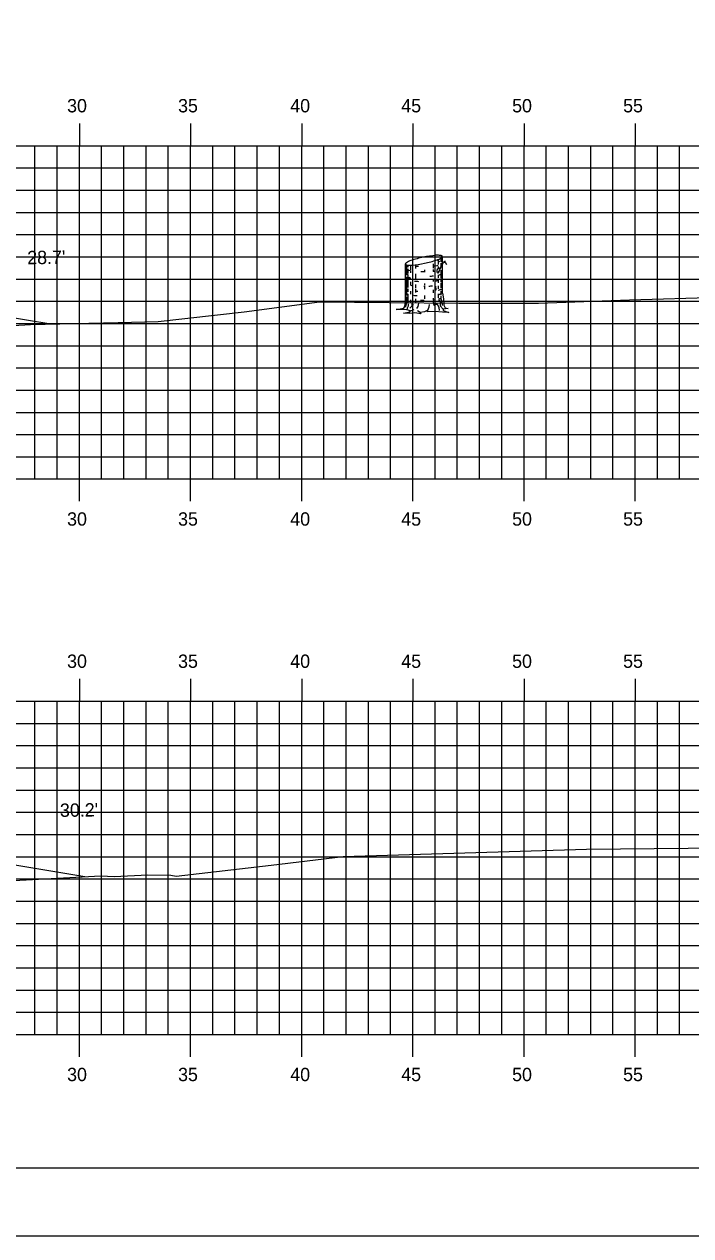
# Model space of a CAD drawing. Extents: x 1048565 to 1048735, y 781387 to 781497.
# Drawn here: x 1048675.4 to 1048705.4, y 781387.3 to 781441.8 of the extents above; entities that cross this region are included whole.
import ezdxf

# ---------------------------------------------------------------- set-up
doc = ezdxf.new("R2010")
doc.units = 0
for name, color, linetype in [('ANNOTATION', 7, 'Continuous'), ('BORDER', 7, 'Continuous'), ('D_Roadway_SlopeLines', 7, 'Continuous'), ('H_V ANNOTATION', 7, 'Continuous'), ('M_Trees_Conifer_Pay', 7, 'Continuous'), ('MAJOR', 7, 'Continuous'), ('MINOR', 7, 'Continuous'), ('PLOT BOUNDARY', 7, 'Continuous'), ('S_Roadway_Centerline', 7, 'Continuous')]:
    doc.layers.add(name, color=color, linetype=linetype)

msp = doc.modelspace()

# ---------------------------------------------------------------- linework, layer by layer
at = {"layer": 'BORDER'}
msp.add_lwpolyline([(1048572.876, 781390.375), (1048732.876, 781390.375), (1048732.876, 781495.375), (1048572.876, 781495.375)], close=True, dxfattribs=at)
at = {"layer": 'D_Roadway_SlopeLines'}
for points in [[(1048673.288, 781428.903), (1048676.593, 781428.352)], [(1048674.618, 781404.065), (1048678.119, 781403.481)]]:
    msp.add_lwpolyline(points, dxfattribs=at)
at = {"layer": 'M_Trees_Conifer_Pay'}
for p, q in [((1048692.54, 781429.33), (1048692.54, 781431.052)), ((1048692.587, 781431.015), (1048692.587, 781430.544)), ((1048692.645, 781431.004), (1048692.645, 781430.906)), ((1048692.771, 781430.996), (1048692.771, 781430.764)), ((1048692.991, 781431.016), (1048692.991, 781430.848)), ((1048693.787, 781431.058), (1048693.787, 781430.859)), ((1048694.015, 781431.254), (1048694.015, 781431.031)), ((1048694.015, 781430.943), (1048694.015, 781430.895)), ((1048694.132, 781431.315), (1048694.132, 781431.153)), ((1048694.132, 781431.085), (1048694.132, 781430.957)), ((1048694.204, 781429.741), (1048694.204, 781431.388)), ((1048692.587, 781430.479), (1048692.587, 781430.171)), ((1048692.645, 781430.832), (1048692.645, 781430.628)), ((1048692.645, 781430.57), (1048692.645, 781430.371)), ((1048692.771, 781430.723), (1048692.771, 781430.649)), ((1048692.991, 781430.611), (1048692.991, 781430.374)), ((1048693.396, 781430.785), (1048693.396, 781430.689)), ((1048693.787, 781430.801), (1048693.787, 781430.712)), ((1048693.787, 781430.365), (1048693.787, 781430.26)), ((1048694.015, 781430.56), (1048694.015, 781430.428)), ((1048694.072, 781430.76), (1048694.021, 781430.7)), ((1048694.132, 781430.77), (1048694.132, 781430.434)), ((1048694.132, 781430.397), (1048694.132, 781430.235)), ((1048692.587, 781430.124), (1048692.587, 781429.632)), ((1048692.645, 781430.323), (1048692.645, 781429.987)), ((1048692.645, 781429.934), (1048692.645, 781429.798)), ((1048692.771, 781430.245), (1048692.771, 781430.107)), ((1048692.771, 781429.835), (1048692.771, 781429.693)), ((1048692.991, 781430.13), (1048692.991, 781429.977)), ((1048692.991, 781429.934), (1048692.991, 781429.761)), ((1048693.396, 781430.171), (1048693.396, 781430.097)), ((1048693.396, 781430.072), (1048693.396, 781429.924)), ((1048693.787, 781429.893), (1048693.787, 781429.746)), ((1048694.015, 781430.317), (1048694.015, 781430.208)), ((1048694.015, 781430.072), (1048694.015, 781429.93)), ((1048694.132, 781430.187), (1048694.132, 781429.971)), ((1048694.132, 781429.94), (1048694.132, 781429.866)), ((1048694.132, 781429.825), (1048694.132, 781429.652)), ((1048692.587, 781429.578), (1048692.587, 781429.33)), ((1048692.645, 781429.699), (1048692.645, 781429.321)), ((1048692.771, 781429.432), (1048692.771, 781429.337)), ((1048692.991, 781429.483), (1048692.991, 781429.33)), ((1048693.396, 781429.632), (1048693.396, 781429.479)), ((1048693.787, 781429.514), (1048693.787, 781429.426)), ((1048694.015, 781429.703), (1048694.015, 781429.531)), ((1048692.771, 781428.937), (1048692.934, 781429.001)), ((1048693.208, 781428.873), (1048693.082, 781428.937))]:
    msp.add_line(p, q, dxfattribs=at)
for points in [[(1048694.021, 781430.886), (1048694.058, 781430.811), (1048694.105, 781430.869), (1048694.163, 781430.937), (1048694.255, 781431.13), (1048694.319, 781431.178), (1048694.35, 781431.184)], [(1048694.035, 781430.632), (1048694.072, 781430.76), (1048694.136, 781430.875), (1048694.166, 781430.943), (1048694.235, 781431.089)], [(1048694.25, 781431.119), (1048694.325, 781431.126), (1048694.397, 781431.027)], [(1048692.719, 781430.358), (1048692.713, 781430.453), (1048692.756, 781430.43), (1048692.756, 781430.336)], [(1048693.987, 781430.848), (1048693.957, 781430.764), (1048693.953, 781430.696), (1048693.983, 781430.632)], [(1048693.858, 781429.959), (1048693.871, 781429.882), (1048693.918, 781429.893), (1048693.905, 781430.059)], [(1048694.204, 781429.741), (1048694.255, 781429.479), (1048694.271, 781429.205), (1048694.329, 781429.08), (1048694.465, 781429.049), (1048694.235, 781429.012), (1048694.235, 781429.012), (1048694.241, 781428.964), (1048694.488, 781428.87), (1048694.214, 781428.886), (1048693.858, 781428.907), (1048693.537, 781428.896), (1048693.543, 781428.979), (1048693.395, 781428.896), (1048693.208, 781428.873), (1048693.232, 781428.806), (1048692.964, 781428.849), (1048692.744, 781428.822), (1048692.451, 781428.839), (1048692.74, 781428.896), (1048692.771, 781428.937), (1048692.608, 781428.995), (1048692.371, 781429.006), (1048692.13, 781429.006), (1048692.472, 781429.063), (1048692.514, 781429.143), (1048692.54, 781429.33)], [(1048692.588, 781429.283), (1048692.567, 781429.205), (1048692.546, 781429.111)], [(1048692.666, 781429.263), (1048692.672, 781429.147), (1048692.619, 781429.059), (1048692.608, 781428.995)], [(1048692.829, 781429.29), (1048692.829, 781429.158), (1048692.74, 781429.059)], [(1048693.055, 781429.049), (1048693.123, 781429.143), (1048693.149, 781429.283)], [(1048693.794, 781429.348), (1048693.804, 781429.222), (1048693.878, 781429.178)], [(1048694.031, 781429.453), (1048694.105, 781429.348), (1048694.109, 781429.174), (1048694.235, 781429.012)], [(1048694.13, 781429.598), (1048694.136, 781429.453), (1048694.183, 781429.384), (1048694.193, 781429.185)], [(1048693.543, 781428.979), (1048693.617, 781429.121), (1048693.627, 781429.222)], [(1048694.072, 781428.958), (1048694.058, 781429.096), (1048693.983, 781429.225)]]:
    msp.add_lwpolyline(points, dxfattribs=at)
for centre, radius, start, end in [((1048694.396, 781426.285), 5.179, 95.3794, 101.7194), ((1048693.985, 781430.643), 0.802, 79.2194, 95.3794), ((1048692.571, 781431.051), 0.0314, 156.5158, 169.2194), ((1048692.566, 781431.052), 0.0264, 169.2194, 180.0315), ((1048692.563, 781431.052), 0.0226, 180.0315, 191.7194), ((1048692.563, 781431.052), 0.0226, 191.7194, 203.4074), ((1048692.591, 781431.043), 0.0527, 146.7194, 156.5158), ((1048692.566, 781431.053), 0.0264, 203.4074, 214.2194), ((1048692.57, 781431.056), 0.0314, 214.2194, 226.923), ((1048692.615, 781431.027), 0.0817, 132.3887, 146.7194), ((1048692.585, 781431.072), 0.0527, 226.923, 236.7194), ((1048692.601, 781431.096), 0.0817, 236.7194, 251.0501), ((1048692.729, 781430.902), 0.251, 124.2194, 132.3887), ((1048692.656, 781431.256), 0.251, 251.0501, 259.2194), ((1048693.039, 781430.446), 0.802, 108.0594, 124.2194), ((1048692.759, 781431.797), 0.802, 259.2194, 275.3794), ((1048694.396, 781426.285), 5.179, 101.7194, 108.0594), ((1048692.348, 781436.155), 5.179, 275.3794, 281.7194), ((1048693.372, 781435.064), 4.124, 264.6955, 266.7331), ((1048692.348, 781436.155), 5.179, 281.7194, 288.0594), ((1048693.372, 781435.064), 4.124, 276.238, 278.1032), ((1048693.873, 781431.547), 0.571, 278.1032, 284.3667), ((1048693.705, 781431.993), 0.802, 288.0594, 304.2194), ((1048693.873, 781431.701), 0.571, 284.4317, 292.4132), ((1048693.873, 781431.547), 0.571, 297.0237, 300), ((1048694.088, 781431.184), 0.251, 71.0501, 79.2194), ((1048694.015, 781431.538), 0.251, 304.2194, 312.3887), ((1048694.072, 781431.356), 0.172, 300, 311.2506), ((1048694.072, 781431.202), 0.172, 300, 311.2506), ((1048694.143, 781431.344), 0.0817, 56.7194, 71.0501), ((1048694.129, 781431.413), 0.0817, 312.3887, 326.7194), ((1048694.145, 781431.273), 0.0624, 311.2506, 330), ((1048694.145, 781431.119), 0.0624, 311.2506, 330), ((1048694.159, 781431.368), 0.0527, 46.923, 56.7194), ((1048694.174, 781431.383), 0.0314, 34.2194, 46.923), ((1048694.153, 781431.397), 0.0527, 326.7194, 336.5158), ((1048694.16, 781431.264), 0.0441, 330, 343.9485), ((1048694.16, 781431.11), 0.0441, 330, 343.9485), ((1048694.178, 781431.386), 0.0264, 23.4074, 34.2194), ((1048694.173, 781431.389), 0.0314, 336.5158, 349.2194), ((1048694.181, 781431.388), 0.0226, 11.7194, 23.4074), ((1048694.181, 781431.388), 0.0226, 0.0315, 11.7194), ((1048694.178, 781431.388), 0.0264, 349.2194, 0.0315), ((1048694.171, 781431.261), 0.0334, 343.9485, 354.2151), ((1048694.171, 781431.107), 0.0334, 343.9485, 354.2151), ((1048692.572, 781430.874), 0.0334, 163.9485, 180), ((1048692.572, 781430.874), 0.0334, 180, 196.0515), ((1048692.572, 781430.427), 0.0334, 163.9485, 180), ((1048692.572, 781430.427), 0.0334, 180, 196.0515), ((1048692.582, 781430.877), 0.0441, 196.0515, 210), ((1048692.582, 781430.43), 0.0441, 196.0515, 210), ((1048692.598, 781430.886), 0.0624, 210, 228.7494), ((1048692.598, 781430.439), 0.0624, 210, 228.7494), ((1048692.671, 781430.969), 0.172, 228.7494, 240), ((1048692.671, 781430.522), 0.172, 228.7494, 240), ((1048692.87, 781431.314), 0.571, 240, 240.3367), ((1048692.87, 781430.867), 0.571, 240, 240.3367), ((1048692.871, 781431.103), 0.571, 240, 247.0587), ((1048692.87, 781431.314), 0.571, 246.8597, 257.9846), ((1048693.371, 781434.831), 4.124, 268.0751, 270), ((1048693.371, 781434.831), 4.124, 270, 270.3581), ((1048693.372, 781434.62), 4.124, 273.7052, 275.9504), ((1048693.371, 781434.831), 4.124, 275.7849, 277.0558), ((1048693.873, 781431.103), 0.571, 284.4493, 297.0429), ((1048693.871, 781430.867), 0.571, 297.1896, 300), ((1048694.071, 781430.522), 0.172, 300, 311.2506), ((1048694.143, 781430.439), 0.0624, 311.2506, 330), ((1048694.159, 781430.43), 0.0441, 330, 343.9485), ((1048694.169, 781430.427), 0.0334, 343.9485, 354.2151), ((1048694.171, 781430.663), 0.0334, 343.9485, 354.2151), ((1048692.572, 781430.217), 0.0334, 163.9485, 180), ((1048692.572, 781430.217), 0.0334, 180, 196.0515), ((1048692.572, 781429.98), 0.0334, 163.9485, 180), ((1048692.572, 781429.98), 0.0334, 180, 196.0515), ((1048692.582, 781430.22), 0.0441, 196.0515, 210), ((1048692.582, 781429.983), 0.0441, 196.0515, 210), ((1048692.598, 781430.229), 0.0624, 210, 228.7494), ((1048692.598, 781429.993), 0.0624, 210, 228.7494), ((1048692.671, 781430.312), 0.172, 228.7494, 240), ((1048692.671, 781430.075), 0.172, 228.7494, 240), ((1048692.87, 781430.657), 0.571, 240, 246.8597), ((1048692.87, 781430.42), 0.571, 240, 246.8597), ((1048692.87, 781430.657), 0.571, 259.2707, 261.8968), ((1048693.371, 781434.175), 4.124, 261.8968, 263.1474), ((1048693.371, 781434.385), 4.124, 264.081, 266.6676), ((1048693.371, 781433.938), 4.124, 264.716, 266.3193), ((1048693.371, 781434.175), 4.124, 270, 270.3581), ((1048693.371, 781434.175), 4.124, 273.1493, 275.4569), ((1048693.371, 781434.385), 4.124, 277.6125, 278.1032), ((1048693.871, 781430.867), 0.571, 278.1032, 286.9296), ((1048693.871, 781430.42), 0.571, 285.3983, 297.1896), ((1048693.871, 781430.657), 0.571, 297.1896, 300), ((1048694.071, 781430.312), 0.172, 300, 311.2506), ((1048694.143, 781430.229), 0.0624, 311.2506, 330), ((1048694.159, 781430.22), 0.0441, 330, 343.9485), ((1048694.169, 781430.217), 0.0334, 343.9485, 354.2151), ((1048692.572, 781429.783), 0.0334, 163.9485, 180), ((1048692.572, 781429.587), 0.0334, 163.9485, 180), ((1048692.572, 781429.587), 0.0334, 180, 196.0515), ((1048692.572, 781429.367), 0.0334, 163.9485, 180), ((1048692.572, 781429.367), 0.0334, 180, 196.0515), ((1048692.582, 781429.59), 0.0441, 196.0515, 210), ((1048692.582, 781429.37), 0.0441, 196.0515, 210), ((1048692.598, 781429.599), 0.0624, 210, 228.7494), ((1048692.598, 781429.379), 0.0624, 210, 228.7494), ((1048692.671, 781429.682), 0.172, 228.7494, 240), ((1048692.671, 781429.462), 0.172, 228.7494, 240), ((1048692.859, 781430.229), 0.571, 241.2369, 248.0268), ((1048692.87, 781430.027), 0.571, 240, 246.8597), ((1048692.87, 781429.807), 0.571, 240, 244.5314), ((1048693.371, 781433.74), 4.124, 263.4991, 265.8397), ((1048693.371, 781433.544), 4.124, 267.8117, 270), ((1048693.371, 781433.544), 4.124, 270, 270.1328), ((1048693.371, 781433.544), 4.124, 275.7849, 276.7896), ((1048693.871, 781430.027), 0.571, 288.5067, 297.2721), ((1048693.871, 781430.223), 0.571, 289.2907, 300), ((1048694.071, 781429.877), 0.172, 300, 311.2506), ((1048694.071, 781429.462), 0.172, 300, 311.2506), ((1048694.143, 781429.795), 0.0624, 311.2506, 330), ((1048694.143, 781429.379), 0.0624, 311.2506, 330), ((1048694.159, 781429.786), 0.0441, 330, 343.9485), ((1048694.159, 781429.37), 0.0441, 330, 343.9485), ((1048694.169, 781429.783), 0.0334, 343.9485, 354.2151), ((1048694.169, 781429.367), 0.0334, 343.9485, 354.2151), ((1048693.371, 781433.324), 4.124, 262.4438, 263.512), ((1048693.371, 781433.324), 4.124, 277.3684, 278.1032), ((1048693.871, 781429.807), 0.571, 278.1032, 281.637)]:
    msp.add_arc(centre, radius, start, end, dxfattribs=at)
at = {"layer": 'MAJOR'}
for p, q in [((1048677.876, 781437.377), (1048677.876, 781436.375)), ((1048682.876, 781437.377), (1048682.876, 781436.375)), ((1048687.876, 781437.377), (1048687.876, 781436.375)), ((1048692.876, 781437.377), (1048692.876, 781436.375)), ((1048697.876, 781437.377), (1048697.876, 781436.375)), ((1048702.876, 781437.377), (1048702.876, 781436.375)), ((1048577.876, 781436.375), (1048717.876, 781436.375)), ((1048577.876, 781436.375), (1048717.876, 781436.375)), ((1048677.876, 781421.375), (1048677.876, 781436.375)), ((1048682.876, 781421.375), (1048682.876, 781436.375)), ((1048687.876, 781421.375), (1048687.876, 781436.375)), ((1048692.876, 781421.375), (1048692.876, 781436.375)), ((1048697.876, 781421.375), (1048697.876, 781436.375)), ((1048702.876, 781421.375), (1048702.876, 781436.375)), ((1048577.876, 781431.375), (1048717.876, 781431.375)), ((1048577.876, 781426.375), (1048717.876, 781426.375)), ((1048577.876, 781421.375), (1048717.876, 781421.375)), ((1048577.876, 781421.375), (1048717.876, 781421.375)), ((1048677.876, 781420.373), (1048677.876, 781421.375)), ((1048682.876, 781420.373), (1048682.876, 781421.375)), ((1048687.876, 781420.373), (1048687.876, 781421.375)), ((1048692.876, 781420.373), (1048692.876, 781421.375)), ((1048697.876, 781420.373), (1048697.876, 781421.375)), ((1048702.876, 781420.373), (1048702.876, 781421.375)), ((1048677.876, 781412.377), (1048677.876, 781411.375)), ((1048682.876, 781412.377), (1048682.876, 781411.375)), ((1048687.876, 781412.377), (1048687.876, 781411.375)), ((1048692.876, 781412.377), (1048692.876, 781411.375)), ((1048697.876, 781412.377), (1048697.876, 781411.375)), ((1048702.876, 781412.377), (1048702.876, 781411.375)), ((1048577.876, 781411.375), (1048717.876, 781411.375)), ((1048577.876, 781411.375), (1048717.876, 781411.375)), ((1048677.876, 781396.375), (1048677.876, 781411.375)), ((1048682.876, 781396.375), (1048682.876, 781411.375)), ((1048687.876, 781396.375), (1048687.876, 781411.375)), ((1048692.876, 781396.375), (1048692.876, 781411.375)), ((1048697.876, 781396.375), (1048697.876, 781411.375)), ((1048702.876, 781396.375), (1048702.876, 781411.375)), ((1048577.876, 781406.375), (1048717.876, 781406.375)), ((1048577.876, 781401.375), (1048717.876, 781401.375)), ((1048577.876, 781396.375), (1048717.876, 781396.375)), ((1048577.876, 781396.375), (1048717.876, 781396.375)), ((1048677.876, 781395.373), (1048677.876, 781396.375)), ((1048682.876, 781395.373), (1048682.876, 781396.375)), ((1048687.876, 781395.373), (1048687.876, 781396.375)), ((1048692.876, 781395.373), (1048692.876, 781396.375)), ((1048697.876, 781395.373), (1048697.876, 781396.375)), ((1048702.876, 781395.373), (1048702.876, 781396.375))]:
    msp.add_line(p, q, dxfattribs=at)
at = {"layer": 'MINOR'}
for p, q in [((1048675.876, 781421.375), (1048675.876, 781436.375)), ((1048676.876, 781421.375), (1048676.876, 781436.375)), ((1048678.876, 781421.375), (1048678.876, 781436.375)), ((1048679.876, 781421.375), (1048679.876, 781436.375)), ((1048680.876, 781421.375), (1048680.876, 781436.375)), ((1048681.876, 781421.375), (1048681.876, 781436.375)), ((1048683.876, 781421.375), (1048683.876, 781436.375)), ((1048684.876, 781421.375), (1048684.876, 781436.375)), ((1048685.876, 781421.375), (1048685.876, 781436.375)), ((1048686.876, 781421.375), (1048686.876, 781436.375)), ((1048688.876, 781421.375), (1048688.876, 781436.375)), ((1048689.876, 781421.375), (1048689.876, 781436.375)), ((1048690.876, 781421.375), (1048690.876, 781436.375)), ((1048691.876, 781421.375), (1048691.876, 781436.375)), ((1048693.876, 781421.375), (1048693.876, 781436.375)), ((1048694.876, 781421.375), (1048694.876, 781436.375)), ((1048695.876, 781421.375), (1048695.876, 781436.375)), ((1048696.876, 781421.375), (1048696.876, 781436.375)), ((1048698.876, 781421.375), (1048698.876, 781436.375)), ((1048699.876, 781421.375), (1048699.876, 781436.375)), ((1048700.876, 781421.375), (1048700.876, 781436.375)), ((1048701.876, 781421.375), (1048701.876, 781436.375)), ((1048703.876, 781421.375), (1048703.876, 781436.375)), ((1048704.876, 781421.375), (1048704.876, 781436.375)), ((1048577.876, 781435.375), (1048717.876, 781435.375)), ((1048577.876, 781434.375), (1048717.876, 781434.375)), ((1048577.876, 781433.375), (1048717.876, 781433.375)), ((1048577.876, 781432.375), (1048717.876, 781432.375)), ((1048577.876, 781430.375), (1048717.876, 781430.375)), ((1048577.876, 781429.375), (1048717.876, 781429.375)), ((1048577.876, 781428.375), (1048717.876, 781428.375)), ((1048577.876, 781427.375), (1048717.876, 781427.375)), ((1048577.876, 781425.375), (1048717.876, 781425.375)), ((1048577.876, 781424.375), (1048717.876, 781424.375)), ((1048577.876, 781423.375), (1048717.876, 781423.375)), ((1048577.876, 781422.375), (1048717.876, 781422.375)), ((1048675.876, 781396.375), (1048675.876, 781411.375)), ((1048676.876, 781396.375), (1048676.876, 781411.375)), ((1048678.876, 781396.375), (1048678.876, 781411.375)), ((1048679.876, 781396.375), (1048679.876, 781411.375)), ((1048680.876, 781396.375), (1048680.876, 781411.375)), ((1048681.876, 781396.375), (1048681.876, 781411.375)), ((1048683.876, 781396.375), (1048683.876, 781411.375)), ((1048684.876, 781396.375), (1048684.876, 781411.375)), ((1048685.876, 781396.375), (1048685.876, 781411.375)), ((1048686.876, 781396.375), (1048686.876, 781411.375)), ((1048688.876, 781396.375), (1048688.876, 781411.375)), ((1048689.876, 781396.375), (1048689.876, 781411.375)), ((1048690.876, 781396.375), (1048690.876, 781411.375)), ((1048691.876, 781396.375), (1048691.876, 781411.375)), ((1048693.876, 781396.375), (1048693.876, 781411.375)), ((1048694.876, 781396.375), (1048694.876, 781411.375)), ((1048695.876, 781396.375), (1048695.876, 781411.375)), ((1048696.876, 781396.375), (1048696.876, 781411.375)), ((1048698.876, 781396.375), (1048698.876, 781411.375)), ((1048699.876, 781396.375), (1048699.876, 781411.375)), ((1048700.876, 781396.375), (1048700.876, 781411.375)), ((1048701.876, 781396.375), (1048701.876, 781411.375)), ((1048703.876, 781396.375), (1048703.876, 781411.375)), ((1048704.876, 781396.375), (1048704.876, 781411.375)), ((1048577.876, 781410.375), (1048717.876, 781410.375)), ((1048577.876, 781409.375), (1048717.876, 781409.375)), ((1048577.876, 781408.375), (1048717.876, 781408.375)), ((1048577.876, 781407.375), (1048717.876, 781407.375)), ((1048577.876, 781405.375), (1048717.876, 781405.375)), ((1048577.876, 781404.375), (1048717.876, 781404.375)), ((1048577.876, 781403.375), (1048717.876, 781403.375)), ((1048577.876, 781402.375), (1048717.876, 781402.375)), ((1048577.876, 781400.375), (1048717.876, 781400.375)), ((1048577.876, 781399.375), (1048717.876, 781399.375)), ((1048577.876, 781398.375), (1048717.876, 781398.375)), ((1048577.876, 781397.375), (1048717.876, 781397.375))]:
    msp.add_line(p, q, dxfattribs=at)
at = {"layer": 'PLOT BOUNDARY'}
msp.add_lwpolyline([(1048564.783, 781387.316), (1048734.783, 781387.316), (1048734.783, 781497.316), (1048564.783, 781497.316)], close=True, dxfattribs=at)
at = {"layer": 'S_Roadway_Centerline'}
for points in [[(1048669.378, 781427.97), (1048675.683, 781428.333), (1048679.625, 781428.416), (1048681.427, 781428.461), (1048685.296, 781428.892), (1048688.675, 781429.345), (1048694.948, 781429.287), (1048698.532, 781429.287), (1048702.622, 781429.431), (1048706.691, 781429.559), (1048710.995, 781429.608), (1048715.425, 781429.683), (1048717.876, 781429.805)], [(1048670.427, 781403.069), (1048678.84, 781403.52), (1048679.442, 781403.484), (1048680.955, 781403.553), (1048681.997, 781403.548), (1048682.236, 781403.502), (1048686.508, 781403.998), (1048689.749, 781404.385), (1048700.682, 781404.709), (1048712.879, 781404.832), (1048715.877, 781404.879), (1048717.876, 781404.977)]]:
    msp.add_lwpolyline(points, dxfattribs=at)

# ---------------------------------------------------------------- texts
at = {"layer": 'ANNOTATION'}
for s, p in [("28.7'", (1048675.535, 781431.039)), ("30.2'", (1048677.008, 781406.167))]:
    msp.add_text(s, height=0.6, rotation=0.7396, dxfattribs=at).set_placement(p)
at = {"layer": 'H_V ANNOTATION'}
for s, p in [('30', (1048677.325, 781437.875)), ('35', (1048682.317, 781437.875)), ('40', (1048687.362, 781437.875)), ('45', (1048692.354, 781437.875)), ('50', (1048697.341, 781437.875)), ('55', (1048702.333, 781437.875)), ('30', (1048677.325, 781419.275)), ('35', (1048682.317, 781419.275)), ('40', (1048687.362, 781419.275)), ('45', (1048692.354, 781419.275)), ('50', (1048697.341, 781419.275)), ('55', (1048702.333, 781419.275)), ('30', (1048677.325, 781412.875)), ('35', (1048682.317, 781412.875)), ('40', (1048687.362, 781412.875)), ('45', (1048692.354, 781412.875)), ('50', (1048697.341, 781412.875)), ('55', (1048702.333, 781412.875)), ('30', (1048677.325, 781394.275)), ('35', (1048682.317, 781394.275)), ('40', (1048687.362, 781394.275)), ('45', (1048692.354, 781394.275)), ('50', (1048697.341, 781394.275)), ('55', (1048702.333, 781394.275))]:
    msp.add_text(s, height=0.6, dxfattribs=at).set_placement(p)

doc.saveas('drawing.dxf')
